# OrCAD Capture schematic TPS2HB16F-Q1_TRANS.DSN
size D; title: TPS2HB16F-Q1 40-V, 16-mOhm Dual-Channel Smart High-Side; rev: 1.0; note: Datasheet: SLVSDV7C     EVM: SLVUBD4B; note: Switch
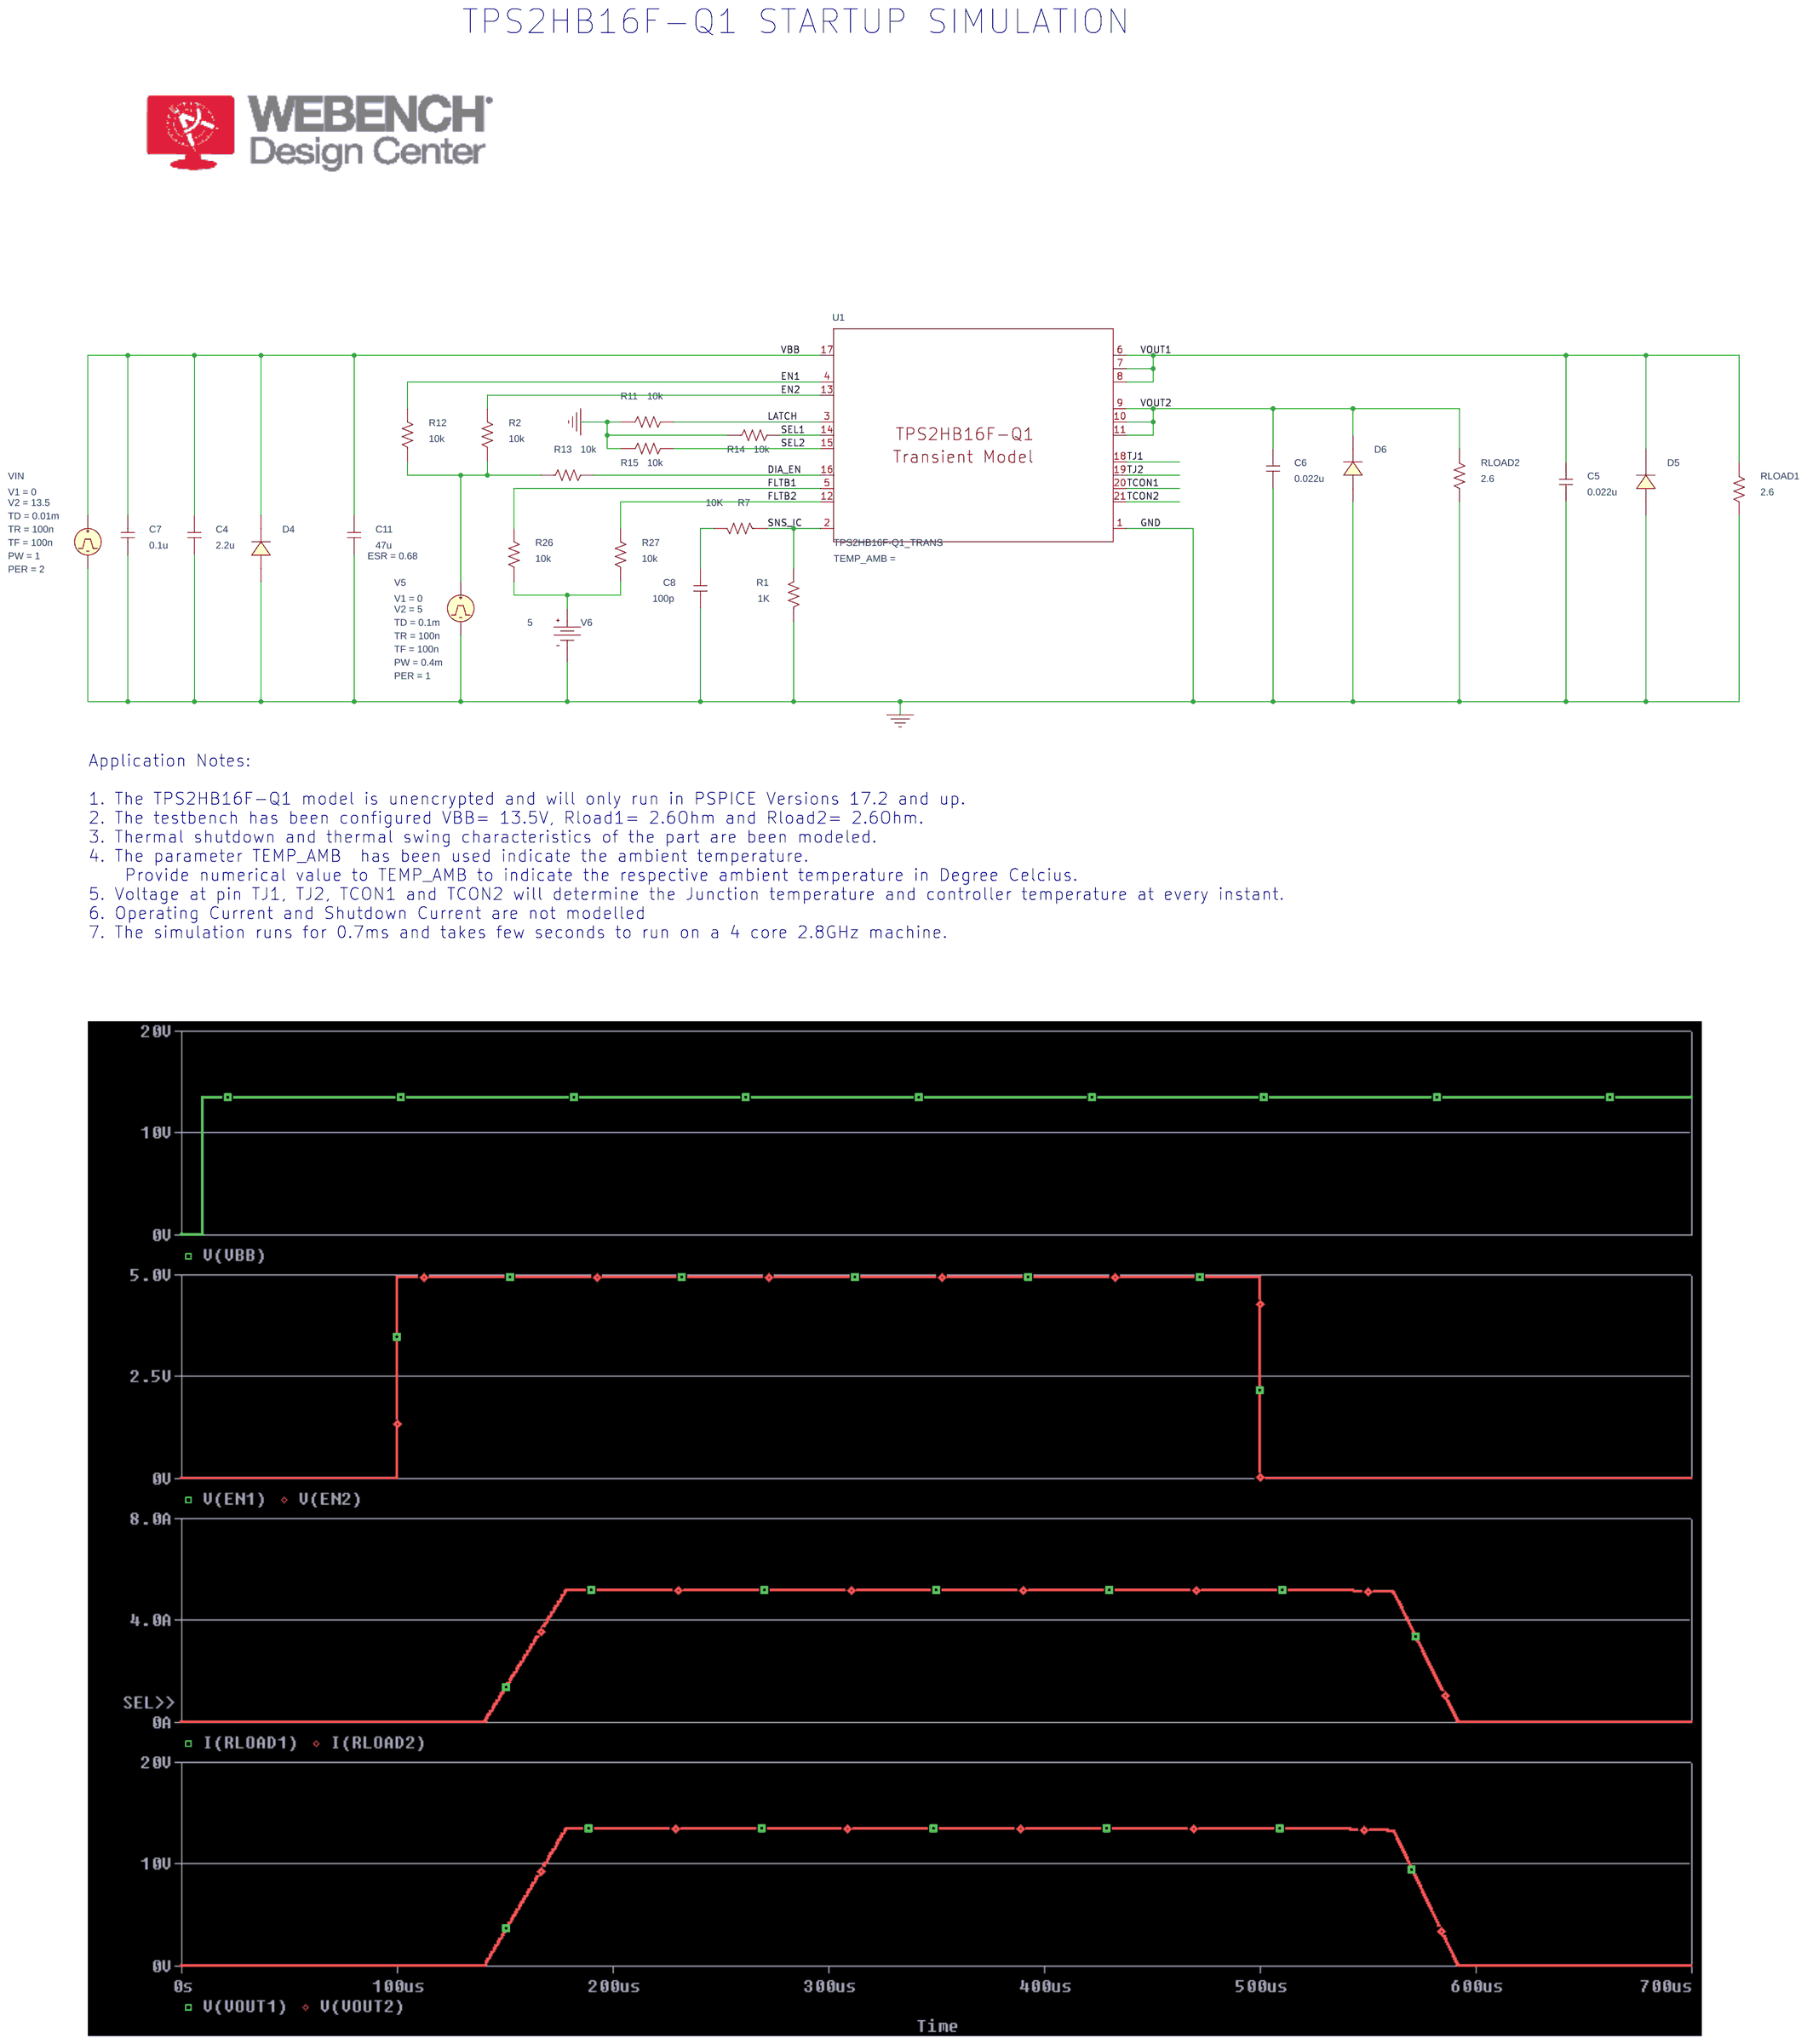
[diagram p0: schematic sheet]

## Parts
C4  2.2u  [RAD/CK05]
C5  0.022u  [RAD/CK05]
C6  0.022u  [RAD/CK05]
C7  0.1u  [RAD/CK05]
C8  100p  [RAD/CK05]
C11  47u  [RAD/CK05]
D4  SMCJ33A
D5  SMCJ33A
D6  SMCJ33A
R1  1K  [AX/RC05]
R2  10k  [AX/RC05]
R7  10K  [AX/RC05]
R11  10k  [AX/RC05]
R12  10k  [AX/RC05]
R13  10k  [AX/RC05]
R14  10k  [AX/RC05]
R15  10k  [AX/RC05]
R26  10k  [AX/RC05]
R27  10k  [AX/RC05]
RLOAD1  2.6  [AX/RC05]
RLOAD2  2.6  [AX/RC05]
U1  TPS2HB16F-Q1_TRANS  [PWP0016M_N]
V5  VPULSE
V6  VDC
VIN  VPULSE

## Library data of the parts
C4-C8 = C
C11 = C: AppProp: InductiveSlave:;SRF:;PrevCap:47u;PrevESL:; ESR: 0.68
D4-D6 = D_D1: PSpiceTemplate: D^@REFDES  %1 %2 @MODEL ?AREA/@AREA/
R1 R2 R7 R11-R15 R26 R27 RLOAD1 RLOAD2 = R
U1 = TPS2HB16F-Q1_TRANS
V5 = VPULSE: PER: 1; PW: 0.4m; TD: 0.1m; TF: 100n; TR: 100n; V1: 0; V2: 5
V6 = VDC: DC: 5
VIN = VPULSE: PER: 2; PW: 1; TD: 0.01m; TF: 100n; TR: 100n; V1: 0; V2: 13.5

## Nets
0: C4.2 C5.2 C6.2 C7.2 C8.2 C11.1 D4.1 D5.1 D6.1 R1.1 R11.1 R14.1 R15.1 RLOAD1.2 RLOAD2.2 U1.1(GND) V5.2(-) V6.1(-) VIN.2(-)
DIA_EN: R13.2 U1.16(DIA_EN)
EN1: R12.2 U1.4(EN1)
EN2: R2.2 U1.13(EN2)
FLTB1: R26.2 U1.5(FLTB1)
FLTB2: R27.2 U1.12(FLTB2)
LATCH: R11.2 U1.3(LATCH)
SEL1: R14.2 U1.14(SEL1)
SEL2: R15.2 U1.15(SEL2)
SNS_IC: R1.2 R7.1 U1.2(SNS)
TCON1: U1.20(TCON1)
TCON2: U1.21(TCON2)
TJ1: U1.18(TJ1)
TJ2: U1.19(TJ2)
VBB: C4.1 C7.1 C11.2 D4.2 U1.17(VBB) VIN.1(+)
VOUT1: C5.1 D5.2 RLOAD1.1 U1.6(VOUT1_0) U1.7(VOUT1_1) U1.8(VOUT1_2)
VOUT2: C6.1 D6.2 RLOAD2.1 U1.9(VOUT2_0) U1.10(VOUT2_1) U1.11(VOUT2_2)
N12697: R2.1 R12.1 R13.1 V5.1(+)
N13391: C8.1 R7.2
N16591: R26.1 R27.1 V6.0(+)

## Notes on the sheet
- TPS2HB16F-Q1 STARTUP SIMULATION
- Application Notes:
  1. The TPS2HB16F-Q1 model is unencrypted and will only run in PSPICE Versions 17.2 and up.
  2. The testbench has been configured VBB= 13.5V, Rload1= 2.6Ohm and Rload2= 2.6Ohm.
  3. Thermal shutdown and thermal swing characteristics of the part are been modeled.
  4. The parameter TEMP_AMB  has been used indicate the ambient temperature.
      Provide numerical value to TEMP_AMB to indicate the respective ambient temperature in Degree Celcius.
  5. Voltage at pin TJ1, TJ2, TCON1 and TCON2 will determine the Junction temperature and controller temperature at every instant.
  6. Operating Current and Shutdown Current are not modelled
  7. The simulation runs for 0.7ms and takes few seconds to run on a 4 core 2.8GHz machine.
